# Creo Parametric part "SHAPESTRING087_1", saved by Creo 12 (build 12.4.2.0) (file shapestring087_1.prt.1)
Units: Custom; MM, KILOGRAM, SECS

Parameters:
  PTC_WM_ITERATION = "0"
  PTC_WM_VERSION = "-.0"
  PTC_WM_LIFECYCLE_STATE = "In Work"
  PTC_WM_LIFECYCLE = "MO_CADDocument"
  PTC_WM_CREATED_BY = "Maximilian Roepper (Z0017RMS: MO)"
  PTC_WM_CREATED_ON = "18-Sep-26 11:36:42 AM"
  PTC_WM_MODIFIED_BY = "Maximilian Roepper (Z0017RMS: MO)"
  PTC_WM_MODIFIED_ON = "18-Sep-26 11:36:46 AM"
  PDMLINKNUMBER = "PDM000071454782"
  PTC_WM_NAME = "shapestring087_1.prt"
  PTC_WM_NUMBER = "PDM000071454782"

Other parameters: WEIGHT, WEIGHT_FACTOR, WEIGHT_ADD, _MASS_TEMP, _DIFF_TEMP, MC_ERRORS, SUPPLIER

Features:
  1. coordinate system
  2. datum plane "PRT_YZ"
  3. datum plane "PRT_XY"
  4. datum plane "PRT_XZ"
  5. coordinate system
  6. datum axis
  7. datum axis
  8. datum axis
  9. coordinate system
  10. imported feature
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
Other named items: PRT, SIEMENS_MO, DRW_VIEW_ORG, PRT_X, PRT_Y, PRT_Z, CS0, ROUGH_GROB

Layers: 00_STD_CSYS-KSYS, 01_STD_PLANES-EBENEN, 02_STD_AXES-ACHSEN, 03_STD_CSYS-KSYS, 24_IMPORT_FEAT-IMPORT_KE, INTFCLR

Surfaces: 1 plane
